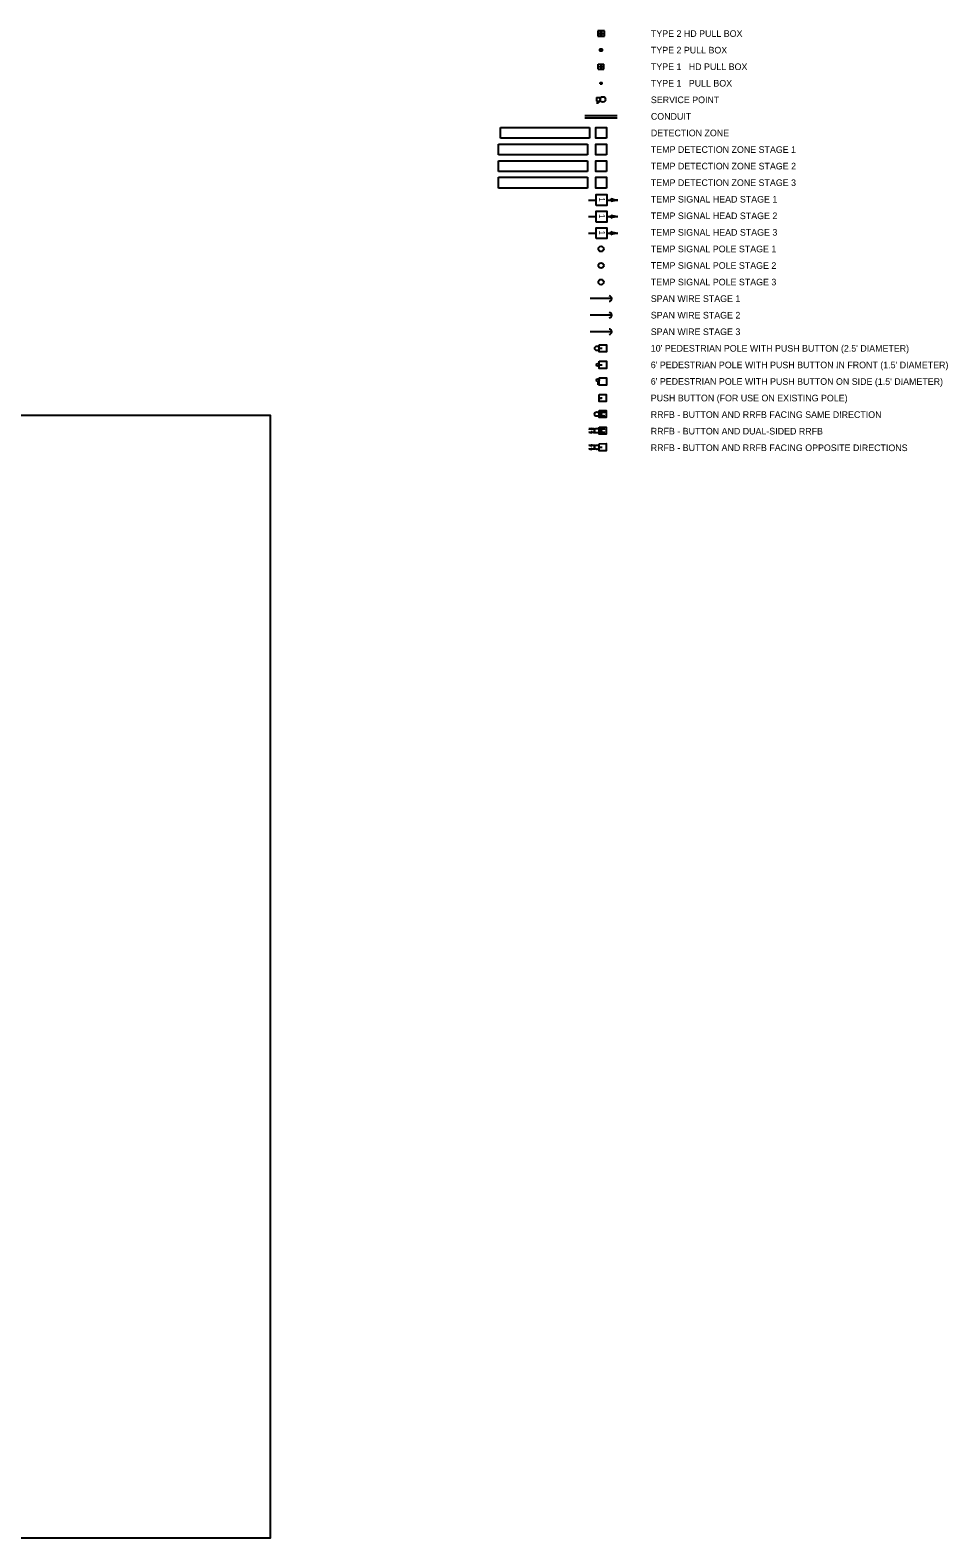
# Model space of a CAD drawing. Extents: x 994065 to 999017, y 1985203 to 1987174.
# Drawn here: x 995155 to 995671, y 1985348 to 1986195 of the extents above; entities that cross this region are included whole.
import ezdxf

# ---------------------------------------------------------------- set-up
doc = ezdxf.new("R2010")
doc.units = 0
for name, color, linetype in [('_CIVIL_CONSTRUCTION', 7, 'Continuous'), ('DSN_Drain_Alignment_ArDOT_BMCD_Rt', 7, 'Continuous'), ('DSN_DRAIN_Analytics', 7, 'Continuous'), ('DSN_DRAIN_Analytics_ArDOT_BMCD_Rt', 7, 'Continuous'), ('DSN_DRAIN_Storm-Sewer', 7, 'Continuous'), ('DSN_RDWY_Alignment Annotation', 7, 'Continuous'), ('DSN_ROW_Line-Annotation', 7, 'Continuous'), ('DSN_ROW_Point', 7, 'Continuous'), ('EX_ALIGNMENT', 7, 'Continuous'), ('EX_CONTOUR_ANNOT_MAJOR', 7, 'Continuous'), ('EX_ROW', 7, 'Continuous'), ('EX_ROW_Annotation', 7, 'Continuous'), ('EX_TERRAIN_BOUNDARY', 7, 'Continuous'), ('Level 23', 7, 'Continuous'), ('S_HWY_SYMBOLS', 7, 'Continuous'), ('S_HWY_TEXT', 7, 'Continuous'), ('S_ORTHO_IMAGE', 7, 'Continuous')]:
    doc.layers.add(name, color=color, linetype=linetype)

msp = doc.modelspace()

# ---------------------------------------------------------------- linework, layer by layer
at = {"layer": '_CIVIL_CONSTRUCTION'}
for p, q in [((995418.2, 1986121.45), (995468.2, 1986121.45)), ((995418.2, 1986115.45), (995418.2, 1986121.45)), ((995468.2, 1986121.45), (995468.2, 1986115.45)), ((995468.2, 1986115.45), (995418.2, 1986115.45))]:
    msp.add_line(p, q, dxfattribs=at)
msp.add_lwpolyline([(995478.87, 1986115.45), (995472.87, 1986115.45), (995472.87, 1986121.45), (995478.87, 1986121.45)], close=True, dxfattribs=at)
at = {"layer": 'DSN_Drain_Alignment_ArDOT_BMCD_Rt'}
for p, q in [((995474.28, 1986175.61), (995477.47, 1986175.61)), ((995474.28, 1986172.88), (995474.28, 1986175.61)), ((995474.28, 1986172.88), (995477.47, 1986172.88)), ((995475.28, 1986173.88), (995475.28, 1986174.61)), ((995475.28, 1986174.61), (995476.47, 1986174.61)), ((995475.28, 1986173.88), (995476.47, 1986173.88)), ((995476.47, 1986173.88), (995476.47, 1986174.61)), ((995477.47, 1986172.88), (995477.47, 1986175.61)), ((995475.28, 1986164.58), (995475.28, 1986165.31)), ((995475.28, 1986165.31), (995476.47, 1986165.31)), ((995475.28, 1986164.58), (995476.47, 1986164.58)), ((995476.47, 1986164.58), (995476.47, 1986165.31))]:
    msp.add_line(p, q, dxfattribs=at)
at = {"layer": 'DSN_DRAIN_Analytics'}
for p, q in [((995419.36, 1986140.05), (995469.36, 1986140.05)), ((995419.36, 1986134.05), (995419.36, 1986140.05)), ((995469.36, 1986134.05), (995419.36, 1986134.05)), ((995469.36, 1986140.05), (995469.36, 1986134.05))]:
    msp.add_line(p, q, dxfattribs=at)
msp.add_lwpolyline([(995478.88, 1986134.05), (995472.88, 1986134.05), (995472.88, 1986140.05), (995478.88, 1986140.05)], close=True, dxfattribs=at)
at = {"layer": 'DSN_DRAIN_Analytics_ArDOT_BMCD_Rt'}
for points in [[(995474.83, 1986018.15), (995478.83, 1986018.15), (995478.83, 1986014.15), (995474.83, 1986014.15)], [(995474.82, 1986008.85), (995478.82, 1986008.85), (995478.82, 1986004.85), (995474.82, 1986004.85)], [(995474.82, 1985999.55), (995478.82, 1985999.55), (995478.82, 1985995.55), (995474.82, 1985995.55)], [(995474.81, 1985990.25), (995478.81, 1985990.25), (995478.81, 1985986.25), (995474.81, 1985986.25)], [(995474.73, 1985981.22), (995478.73, 1985981.23), (995478.74, 1985977.23), (995474.74, 1985977.22)], [(995474.75, 1985971.92), (995478.75, 1985971.93), (995478.76, 1985967.93), (995474.76, 1985967.92)], [(995474.77, 1985962.62), (995478.77, 1985962.63), (995478.77, 1985958.63), (995474.77, 1985958.62)]]:
    msp.add_lwpolyline(points, close=True, dxfattribs=at)
at = {"layer": 'DSN_DRAIN_Storm-Sewer'}
for p, q in [((995473.37, 1986156.9), (995473.37, 1986154.9)), ((995473.37, 1986156.9), (995475.37, 1986156.9)), ((995473.37, 1986154.9), (995475.37, 1986154.9)), ((995473.37, 1986153.9), (995474.37, 1986153.9)), ((995474.37, 1986154.9), (995474.37, 1986153.9)), ((995475.37, 1986156.9), (995475.37, 1986154.9)), ((995466.8, 1986146.84), (995484.94, 1986146.84)), ((995466.8, 1986145.52), (995484.94, 1986145.52))]:
    msp.add_line(p, q, dxfattribs=at)
msp.add_circle((995476.87, 1986155.9), 1.5, dxfattribs=at)
at = {"layer": 'DSN_RDWY_Alignment Annotation'}
for p, q in [((995468.75, 1986099.38), (995473.1, 1986099.38)), ((995479.16, 1986099.4), (995485.2, 1986099.4))]:
    msp.add_line(p, q, dxfattribs=at)
msp.add_lwpolyline([(995473.1, 1986096.36), (995473.1, 1986102.43), (995479.16, 1986102.43), (995479.16, 1986096.36)], close=True, dxfattribs=at)
for centre, radius, start, end in [((995479.93, 1986099.4), 1.63, 328.15268, 31.84732), ((995489.61, 1986128.54), 29.47, 253.65357, 261.39168), ((995489.61, 1986070.26), 29.47, 98.60832, 106.34643)]:
    msp.add_arc(centre, radius, start, end, dxfattribs=at)
at = {"layer": 'DSN_ROW_Line-Annotation'}
msp.add_line((995481.83, 1986025.45), (995469.83, 1986025.45), dxfattribs=at)
msp.add_circle((995475.83, 1986053.35), 1.5, dxfattribs=at)
msp.add_arc((995480.33, 1986025.45), 1.5, 270, 90, dxfattribs=at)
at = {"layer": 'DSN_ROW_Point'}
for p, q in [((995468.74, 1986090.08), (995473.09, 1986090.08)), ((995479.15, 1986090.1), (995485.2, 1986090.1))]:
    msp.add_line(p, q, dxfattribs=at)
msp.add_lwpolyline([(995473.09, 1986087.06), (995473.09, 1986093.13), (995479.15, 1986093.13), (995479.15, 1986087.06)], close=True, dxfattribs=at)
for centre, radius, start, end in [((995479.93, 1986090.1), 1.63, 328.15268, 31.84732), ((995489.61, 1986119.24), 29.47, 253.65357, 261.39168), ((995489.61, 1986060.96), 29.47, 98.60832, 106.34643)]:
    msp.add_arc(centre, radius, start, end, dxfattribs=at)
at = {"layer": 'EX_ALIGNMENT'}
msp.add_line((995481.83, 1986034.75), (995469.83, 1986034.75), dxfattribs=at)
msp.add_circle((995475.84, 1986062.65), 1.5, dxfattribs=at)
msp.add_arc((995480.33, 1986034.75), 1.5, 270, 90, dxfattribs=at)
at = {"layer": 'EX_CONTOUR_ANNOT_MAJOR'}
for p, q in [((995477.75, 1986194.3), (995474, 1986194.3)), ((995474, 1986194.3), (995474, 1986191.38)), ((995475, 1986192.38), (995475, 1986193.3)), ((995475, 1986193.3), (995476.75, 1986193.3)), ((995475, 1986193.3), (995475, 1986192.38)), ((995476.75, 1986193.3), (995475, 1986193.3)), ((995476.75, 1986192.38), (995476.75, 1986193.3)), ((995476.75, 1986192.38), (995476.75, 1986193.3)), ((995477.75, 1986191.38), (995477.75, 1986194.3)), ((995474, 1986191.38), (995477.75, 1986191.38)), ((995475, 1986192.38), (995476.75, 1986192.38)), ((995475, 1986192.38), (995476.75, 1986192.38)), ((995475, 1986184.01), (995475, 1986183.09)), ((995476.75, 1986184.01), (995475, 1986184.01)), ((995475, 1986183.09), (995476.75, 1986183.09)), ((995476.75, 1986183.09), (995476.75, 1986184.01)), ((995474.83, 1986016.15), (995476.14, 1986016.15)), ((995476.14, 1986015.71), (995476.14, 1986016.58)), ((995476.14, 1986006.41), (995476.14, 1986007.28)), ((995474.82, 1986006.85), (995476.14, 1986006.85)), ((995473.63, 1985996.23), (995474.5, 1985996.23)), ((995474.07, 1985997.55), (995474.07, 1985996.23)), ((995474.81, 1985988.25), (995476.13, 1985988.25)), ((995476.13, 1985987.81), (995476.13, 1985988.68)), ((995474.74, 1985979.22), (995476.05, 1985979.22)), ((995476.05, 1985978.78), (995476.05, 1985979.66)), ((995474.75, 1985969.92), (995476.07, 1985969.92)), ((995476.07, 1985969.48), (995476.07, 1985970.36)), ((995474.77, 1985960.62), (995476.09, 1985960.62)), ((995476.09, 1985960.18), (995476.09, 1985961.06))]:
    msp.add_line(p, q, dxfattribs=at)
at = {"layer": 'EX_ROW'}
for p, q in [((995418.19, 1986112.15), (995468.19, 1986112.15)), ((995418.19, 1986106.15), (995418.19, 1986112.15)), ((995468.19, 1986112.15), (995468.19, 1986106.15)), ((995468.19, 1986106.15), (995418.19, 1986106.15))]:
    msp.add_line(p, q, dxfattribs=at)
msp.add_lwpolyline([(995478.87, 1986106.15), (995472.87, 1986106.15), (995472.87, 1986112.15), (995478.87, 1986112.15)], close=True, dxfattribs=at)
at = {"layer": 'EX_ROW_Annotation'}
for p, q in [((995468.74, 1986080.78), (995473.09, 1986080.78)), ((995479.15, 1986080.8), (995485.19, 1986080.8))]:
    msp.add_line(p, q, dxfattribs=at)
msp.add_lwpolyline([(995473.09, 1986077.76), (995473.09, 1986083.83), (995479.15, 1986083.83), (995479.15, 1986077.76)], close=True, dxfattribs=at)
for centre, radius, start, end in [((995479.92, 1986080.8), 1.63, 328.15268, 31.84732), ((995489.6, 1986109.94), 29.47, 253.65357, 261.39168), ((995489.6, 1986051.66), 29.47, 98.60832, 106.34643)]:
    msp.add_arc(centre, radius, start, end, dxfattribs=at)
at = {"layer": 'EX_TERRAIN_BOUNDARY'}
for p, q in [((995474.74, 1985979.22), (995474.99, 1985979.22)), ((995474.99, 1985977.72), (995474.98, 1985980.72)), ((995474.98, 1985980.21), (995478, 1985980.22)), ((995474.99, 1985978.21), (995478.01, 1985978.22)), ((995472, 1985970.91), (995468.98, 1985970.91)), ((995472, 1985968.91), (995468.98, 1985968.91)), ((995472, 1985971.41), (995472.01, 1985968.41)), ((995472.25, 1985969.91), (995472, 1985969.91)), ((995474.75, 1985969.92), (995475, 1985969.92)), ((995475.01, 1985968.42), (995475, 1985971.42)), ((995475, 1985970.91), (995478.02, 1985970.92)), ((995475, 1985968.91), (995478.03, 1985968.92)), ((995472.02, 1985961.62), (995469, 1985961.62)), ((995472.02, 1985959.62), (995469, 1985959.62)), ((995472.02, 1985962.12), (995472.02, 1985959.12)), ((995472.27, 1985960.62), (995472.02, 1985960.62))]:
    msp.add_line(p, q, dxfattribs=at)
for centre, radius in [((995475.84, 1986071.95), 1.5), ((995473.58, 1986016.15), 1.25), ((995474.07, 1986006.85), 0.75), ((995474.07, 1985998.3), 0.75), ((995473.49, 1985979.22), 1.25), ((995473.5, 1985969.92), 1.25), ((995473.52, 1985960.62), 1.25)]:
    msp.add_circle(centre, radius, dxfattribs=at)
for centre, radius, start, end in [((995475.37, 1985980.21), 0.814, 328.2824, 31.97704), ((995480.18, 1985994.79), 14.74, 253.78329, 261.52141), ((995480.24, 1985965.65), 14.74, 98.73804, 106.47615), ((995475.37, 1985978.21), 0.814, 328.2824, 31.97704), ((995480.18, 1985992.79), 14.74, 253.78329, 261.52141), ((995480.25, 1985963.65), 14.74, 98.73804, 106.47615), ((995466.74, 1985985.47), 14.74, 278.73804, 286.47615), ((995466.81, 1985956.33), 14.74, 73.78329, 81.52141), ((995466.75, 1985983.47), 14.74, 278.73804, 286.47615), ((995466.81, 1985954.33), 14.74, 73.78329, 81.52141), ((995471.61, 1985970.91), 0.814, 148.2824, 211.97704), ((995471.62, 1985968.91), 0.814, 148.2824, 211.97704), ((995475.39, 1985970.91), 0.814, 328.2824, 31.97704), ((995480.19, 1985985.49), 14.74, 253.78329, 261.52141), ((995480.26, 1985956.35), 14.74, 98.73804, 106.47615), ((995475.39, 1985968.91), 0.814, 328.2824, 31.97704), ((995480.2, 1985983.49), 14.74, 253.78329, 261.52141), ((995480.26, 1985954.35), 14.74, 98.73804, 106.47615), ((995466.76, 1985976.18), 14.74, 278.73804, 286.47615), ((995466.82, 1985947.04), 14.74, 73.78329, 81.52141), ((995466.76, 1985974.18), 14.74, 278.73804, 286.47615), ((995466.83, 1985945.04), 14.74, 73.78329, 81.52141), ((995471.63, 1985961.62), 0.814, 148.2824, 211.97704), ((995471.63, 1985959.62), 0.814, 148.2824, 211.97704)]:
    msp.add_arc(centre, radius, start, end, dxfattribs=at)
at = {"layer": 'Level 23'}
msp.add_lwpolyline([(994300.17, 1985348.35), (995290.18, 1985348.35), (995290.18, 1985978.35), (994300.17, 1985978.35)], close=True, dxfattribs=at)
at = {"layer": 'S_HWY_SYMBOLS'}
for p, q in [((995418.2, 1986130.75), (995468.2, 1986130.75)), ((995418.2, 1986124.75), (995418.2, 1986130.75)), ((995468.2, 1986130.75), (995468.2, 1986124.75)), ((995468.2, 1986124.75), (995418.2, 1986124.75))]:
    msp.add_line(p, q, dxfattribs=at)
msp.add_lwpolyline([(995478.87, 1986124.75), (995472.87, 1986124.75), (995472.87, 1986130.75), (995478.87, 1986130.75)], close=True, dxfattribs=at)
at = {"layer": 'S_HWY_TEXT'}
msp.add_line((995481.83, 1986044.05), (995469.83, 1986044.05), dxfattribs=at)
msp.add_arc((995480.33, 1986044.05), 1.5, 270, 90, dxfattribs=at)

# ---------------------------------------------------------------- texts
at = {"layer": 'DSN_RDWY_Alignment Annotation'}
msp.add_text('1', height=3.25, rotation=270, dxfattribs=at).set_placement((995474.75, 1986100.86))
at = {"layer": 'DSN_ROW_Point'}
msp.add_text('1', height=3.25, rotation=270, dxfattribs=at).set_placement((995474.74, 1986091.56))
at = {"layer": 'EX_ROW_Annotation'}
msp.add_text('1', height=3.25, rotation=270, dxfattribs=at).set_placement((995474.74, 1986082.26))
at = {"layer": 'S_ORTHO_IMAGE'}
for s, p in [('TYPE 2 HD PULL BOX', (995503.86, 1986191)), ('TYPE 2 PULL BOX', (995503.85, 1986181.7)), ('TYPE 1   HD PULL BOX', (995503.85, 1986172.4)), ('TYPE 1   PULL BOX', (995503.85, 1986163.1)), ('SERVICE POINT', (995503.84, 1986153.8)), ('CONDUIT', (995503.84, 1986144.5)), ('DETECTION ZONE', (995503.83, 1986135.2)), ('TEMP DETECTION ZONE STAGE 1', (995503.83, 1986125.9)), ('TEMP DETECTION ZONE STAGE 2', (995503.83, 1986116.6)), ('TEMP DETECTION ZONE STAGE 3', (995503.82, 1986107.3)), ('TEMP SIGNAL HEAD STAGE 1', (995503.82, 1986098)), ('TEMP SIGNAL HEAD STAGE 2', (995503.81, 1986088.7)), ('TEMP SIGNAL HEAD STAGE 3', (995503.81, 1986079.4)), ('TEMP SIGNAL POLE STAGE 1', (995503.8, 1986070.1)), ('TEMP SIGNAL POLE STAGE 2', (995503.8, 1986060.8)), ('TEMP SIGNAL POLE STAGE 3', (995503.8, 1986051.5)), ('SPAN WIRE STAGE 1', (995503.79, 1986042.2)), ('SPAN WIRE STAGE 2', (995503.79, 1986032.9)), ('SPAN WIRE STAGE 3', (995503.78, 1986023.6)), ("10' PEDESTRIAN POLE WITH PUSH BUTTON (2.5' DIAMETER)", (995503.78, 1986014.3)), ("6' PEDESTRIAN POLE WITH PUSH BUTTON IN FRONT (1.5' DIAMETER)", (995503.78, 1986005)), ("6' PEDESTRIAN POLE WITH PUSH BUTTON ON SIDE (1.5' DIAMETER)", (995503.77, 1985995.7)), ('PUSH BUTTON (FOR USE ON EXISTING POLE)', (995503.77, 1985986.4)), ('RRFB - BUTTON AND RRFB FACING SAME DIRECTION', (995503.76, 1985977.1)), ('RRFB - BUTTON AND DUAL-SIDED RRFB', (995503.76, 1985967.8)), ('RRFB - BUTTON AND RRFB FACING OPPOSITE DIRECTIONS', (995503.76, 1985958.5))]:
    msp.add_text(s, height=3.72, rotation=359.97484, dxfattribs=at).set_placement(p)

doc.saveas('drawing.dxf')
